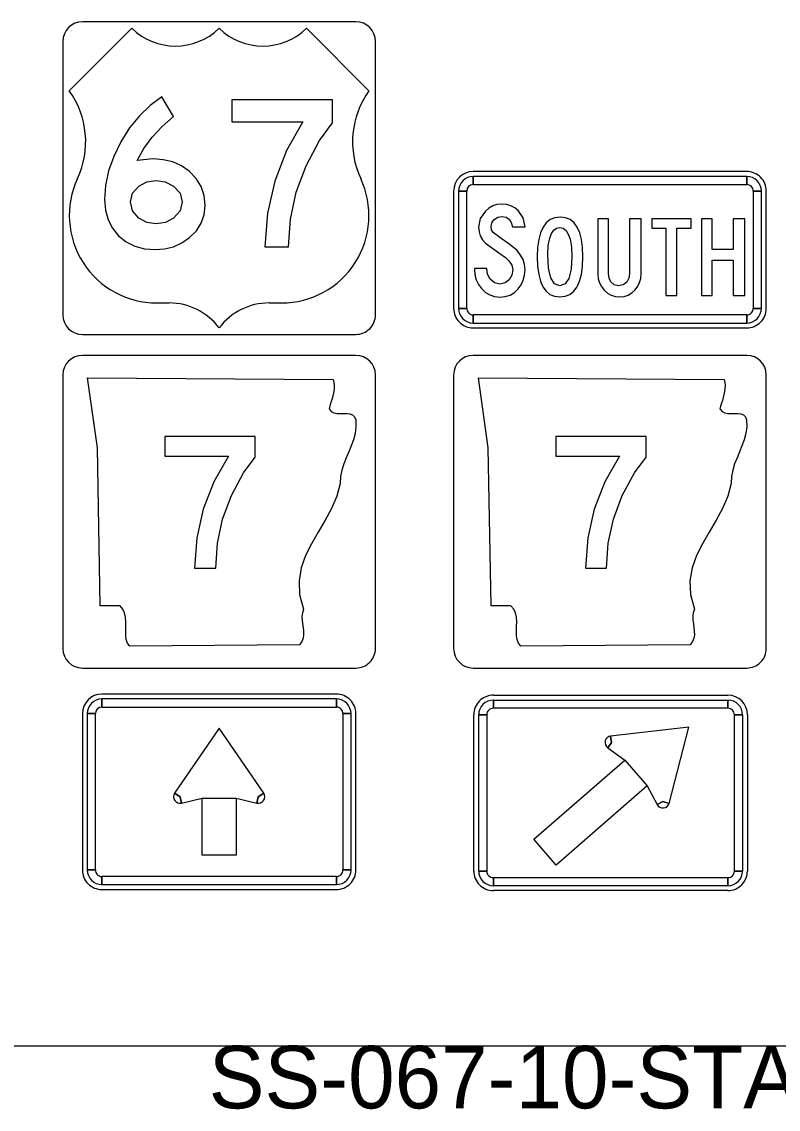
# Model space of a CAD drawing. Extents: x 1001568 to 1002149, y 1840825 to 1841423.
# Drawn here: x 1001897.59 to 1001902.43, y 1841195.06 to 1841202.02 of the extents above; entities that cross this region are included whole.
import ezdxf

# ---------------------------------------------------------------- set-up
doc = ezdxf.new("R2010")
doc.units = 0
for name, color, linetype in [('40', 7, 'Continuous'), ('R_No Plot', 7, 'Continuous'), ('SIGNS', 7, 'Continuous')]:
    doc.layers.add(name, color=color, linetype=linetype)

msp = doc.modelspace()

# ---------------------------------------------------------------- linework, layer by layer
at = {"layer": 'R_No Plot'}
msp.add_line((1001886.4111, 1841195.4691), (1001982.1327, 1841195.4691), dxfattribs=at)
at = {"layer": 'SIGNS'}
for p, q in [((1001899.7246, 1841202.0197), (1001897.9746, 1841202.0197)), ((1001898.2906, 1841201.9781), (1001897.8913, 1841201.5788)), ((1001899.8079, 1841201.5788), (1001899.4086, 1841201.9781)), ((1001897.8496, 1841201.8947), (1001897.8496, 1841200.1447)), ((1001899.8496, 1841200.1447), (1001899.8496, 1841201.8947)), ((1001902.2246, 1841201.0614), (1001900.4746, 1841201.0614)), ((1001900.4746, 1841200.9781), (1001900.4746, 1841201.0302)), ((1001902.2246, 1841201.0302), (1001902.2246, 1841200.9781)), ((1001900.3496, 1841200.9364), (1001900.3496, 1841200.1864)), ((1001900.3808, 1841200.9364), (1001900.4329, 1841200.9364)), ((1001902.2663, 1841200.9364), (1001902.3183, 1841200.9364)), ((1001902.3496, 1841200.1864), (1001902.3496, 1841200.9364)), ((1001898.4503, 1841200.2211), (1001898.5301, 1841200.2211)), ((1001899.169, 1841200.2211), (1001899.2489, 1841200.2211)), ((1001897.8496, 1841200.1447), (1001897.8496, 1841200.1447)), ((1001900.4329, 1841200.1864), (1001900.3808, 1841200.1864)), ((1001900.4746, 1841200.0927), (1001900.4746, 1841200.1447)), ((1001902.2246, 1841200.1447), (1001902.2246, 1841200.0927)), ((1001902.3183, 1841200.1864), (1001902.2663, 1841200.1864)), ((1001897.9746, 1841200.0197), (1001899.7246, 1841200.0197)), ((1001900.4746, 1841200.0614), (1001902.2246, 1841200.0614)), ((1001899.7246, 1841199.8858), (1001897.9746, 1841199.8858)), ((1001902.2246, 1841199.8858), (1001900.4746, 1841199.8858)), ((1001897.8496, 1841199.7608), (1001897.8496, 1841198.0108)), ((1001899.8496, 1841198.0108), (1001899.8496, 1841199.7608)), ((1001900.3496, 1841199.7608), (1001900.3496, 1841198.0108)), ((1001902.3496, 1841198.0108), (1001902.3496, 1841199.7608)), ((1001897.8496, 1841198.0108), (1001897.8496, 1841198.0108)), ((1001900.3496, 1841198.0108), (1001900.3496, 1841198.0108)), ((1001897.9746, 1841197.8858), (1001899.7246, 1841197.8858)), ((1001900.4746, 1841197.8858), (1001902.2246, 1841197.8858)), ((1001899.5996, 1841197.7191), (1001898.0996, 1841197.7191)), ((1001900.6035, 1841197.712), (1001902.1035, 1841197.712)), ((1001898.0996, 1841197.6358), (1001898.0996, 1841197.6879)), ((1001899.5996, 1841197.6879), (1001899.5996, 1841197.6358)), ((1001900.6035, 1841197.6808), (1001900.6035, 1841197.6287)), ((1001902.1035, 1841197.6287), (1001902.1035, 1841197.6808)), ((1001897.9746, 1841197.5941), (1001897.9746, 1841196.5941)), ((1001898.0058, 1841197.5941), (1001898.0579, 1841197.5941)), ((1001899.6413, 1841197.5941), (1001899.6933, 1841197.5941)), ((1001899.7246, 1841196.5941), (1001899.7246, 1841197.5941)), ((1001900.4785, 1841196.587), (1001900.4785, 1841197.587)), ((1001900.5618, 1841197.587), (1001900.5098, 1841197.587)), ((1001902.1973, 1841197.587), (1001902.1452, 1841197.587)), ((1001902.2285, 1841197.587), (1001902.2285, 1841196.587)), ((1001901.3599, 1841197.4094), (1001901.3536, 1841197.4506)), ((1001901.3354, 1841197.3757), (1001901.3599, 1841197.4094)), ((1001898.5996, 1841197.0629), (1001898.5644, 1841197.0851)), ((1001899.1348, 1841197.0851), (1001899.0996, 1841197.0629)), ((1001898.6089, 1841197.0223), (1001898.5996, 1841197.0629)), ((1001899.0996, 1841197.0629), (1001899.0902, 1841197.0223)), ((1001901.688, 1841197.0321), (1001901.6512, 1841197.0125)), ((1001901.7279, 1841197.0201), (1001901.688, 1841197.0321)), ((1001898.0579, 1841196.5941), (1001898.0058, 1841196.5941)), ((1001899.6933, 1841196.5941), (1001899.6413, 1841196.5941)), ((1001898.0996, 1841196.5004), (1001898.0996, 1841196.5524)), ((1001899.5996, 1841196.5524), (1001899.5996, 1841196.5004)), ((1001900.5098, 1841196.587), (1001900.5618, 1841196.587)), ((1001900.6035, 1841196.5454), (1001900.6035, 1841196.4933)), ((1001902.1035, 1841196.4933), (1001902.1035, 1841196.5454)), ((1001902.1452, 1841196.587), (1001902.1973, 1841196.587)), ((1001898.0996, 1841196.4691), (1001899.5996, 1841196.4691)), ((1001902.1035, 1841196.462), (1001900.6035, 1841196.462))]:
    msp.add_line(p, q, dxfattribs=at)
for points in [[(1001897.9746, 1841202.0197), (1001897.9746, 1841202.0197)], [(1001899.7246, 1841202.0197), (1001899.7246, 1841202.0197)], [(1001897.8496, 1841201.8947), (1001897.8496, 1841201.8947)], [(1001898.5582, 1841201.4144), (1001898.4824, 1841201.5388), (1001898.4075, 1841201.4835), (1001898.3393, 1841201.4175), (1001898.2771, 1841201.3401), (1001898.2215, 1841201.252), (1001898.1752, 1841201.1584), (1001898.1427, 1841201.0654), (1001898.1228, 1841200.9732), (1001898.1165, 1841200.882), (1001898.1218, 1841200.8142), (1001898.1389, 1841200.7532), (1001898.1671, 1841200.6988), (1001898.2068, 1841200.651), (1001898.2552, 1841200.6119), (1001898.3102, 1841200.5842), (1001898.3715, 1841200.5676), (1001898.4395, 1841200.5621), (1001898.5003, 1841200.5667), (1001898.5576, 1841200.581), (1001898.6102, 1841200.605), (1001898.6595, 1841200.6389), (1001898.7038, 1841200.6824), (1001898.7355, 1841200.7313), (1001898.7545, 1841200.7855), (1001898.7608, 1841200.8451), (1001898.7543, 1841200.9088), (1001898.7352, 1841200.9665), (1001898.703, 1841201.0181), (1001898.6583, 1841201.0636), (1001898.6079, 1841201.0979), (1001898.5529, 1841201.1227), (1001898.4924, 1841201.1373), (1001898.4272, 1841201.1425), (1001898.3257, 1841201.1322), (1001898.3681, 1841201.2094), (1001898.4211, 1841201.2825), (1001898.4844, 1841201.3505), (1001898.5582, 1841201.4144)], [(1001898.2822, 1841200.867), (1001898.2956, 1841200.9231), (1001898.3358, 1841200.9689), (1001898.388, 1841200.9954), (1001898.4467, 1841201.0043), (1001898.5054, 1841200.9954), (1001898.5584, 1841200.9689), (1001898.5998, 1841200.9234), (1001898.614, 1841200.867), (1001898.5998, 1841200.8093), (1001898.5584, 1841200.7633), (1001898.506, 1841200.7366), (1001898.4467, 1841200.7279), (1001898.3874, 1841200.7366), (1001898.3358, 1841200.7633), (1001898.2956, 1841200.8093), (1001898.2822, 1841200.867)], [(1001901.1765, 1841200.5156), (1001901.1741, 1841200.575), (1001901.1673, 1841200.6267), (1001901.1561, 1841200.6703), (1001901.1403, 1841200.7061), (1001901.1197, 1841200.7338), (1001901.0949, 1841200.7538), (1001901.0655, 1841200.7656), (1001901.0317, 1841200.7697), (1001900.9971, 1841200.7656), (1001900.9672, 1841200.7538), (1001900.9419, 1841200.7338), (1001900.9214, 1841200.7061), (1001900.9053, 1841200.6703), (1001900.8939, 1841200.6267), (1001900.8869, 1841200.575), (1001900.8848, 1841200.5156), (1001900.8868, 1841200.4555), (1001900.8936, 1841200.4037), (1001900.9048, 1841200.3597), (1001900.9206, 1841200.3239), (1001900.9408, 1841200.2959), (1001900.9656, 1841200.276), (1001900.9949, 1841200.2641), (1001901.0287, 1841200.2602), (1001901.0632, 1841200.2641), (1001901.0932, 1841200.276), (1001901.1186, 1841200.2959), (1001901.1395, 1841200.3239), (1001901.1556, 1841200.3597), (1001901.1672, 1841200.4037), (1001901.1741, 1841200.4555), (1001901.1765, 1841200.5156)], [(1001901.1059, 1841200.5179), (1001901.1011, 1841200.4362), (1001901.0867, 1841200.378), (1001901.0627, 1841200.343), (1001901.0294, 1841200.3314), (1001900.9955, 1841200.3438), (1001900.9712, 1841200.3811), (1001900.9568, 1841200.4431), (1001900.952, 1841200.5302), (1001900.9551, 1841200.5881), (1001900.9643, 1841200.6361), (1001900.9755, 1841200.6656), (1001900.99, 1841200.6869), (1001901.0079, 1841200.6995), (1001901.0294, 1841200.7039), (1001901.0505, 1841200.6992), (1001901.0683, 1841200.6853), (1001901.0829, 1841200.662), (1001901.0942, 1841200.6297), (1001901.1029, 1841200.5788), (1001901.1059, 1841200.5179)], [(1001897.9746, 1841200.0197), (1001897.9746, 1841200.0197)], [(1001899.7246, 1841200.0197), (1001899.7246, 1841200.0197)], [(1001897.9746, 1841199.8858), (1001897.9746, 1841199.8858)], [(1001899.7246, 1841199.8858), (1001899.7246, 1841199.8858)], [(1001900.4746, 1841199.8858), (1001900.4746, 1841199.8858)], [(1001902.2246, 1841199.8858), (1001902.2246, 1841199.8858)], [(1001897.8496, 1841199.7608), (1001897.8496, 1841199.7608)], [(1001900.3496, 1841199.7608), (1001900.3496, 1841199.7608)], [(1001897.9746, 1841197.8858), (1001897.9746, 1841197.8858)], [(1001899.7246, 1841197.8858), (1001899.7246, 1841197.8858)], [(1001900.4746, 1841197.8858), (1001900.4746, 1841197.8858)], [(1001902.2246, 1841197.8858), (1001902.2246, 1841197.8858)]]:
    msp.add_lwpolyline(points, dxfattribs=at)
for points in [[(1001899.1423, 1841200.5805), (1001899.2942, 1841200.5805), (1001899.3062, 1841200.7573), (1001899.3433, 1841200.93), (1001899.4053, 1841201.0976), (1001899.492, 1841201.2609), (1001899.5754, 1841201.373), (1001899.5754, 1841201.5204), (1001898.931, 1841201.5204), (1001898.931, 1841201.3795), (1001899.3851, 1841201.3795), (1001899.2802, 1841201.1953), (1001899.2051, 1841201.0008), (1001899.159, 1841200.7959)], [(1001902.2246, 1841201.0302), (1001900.4746, 1841201.0302), (1001900.4746, 1841200.9781), (1001902.2246, 1841200.9781), (1001902.2246, 1841201.0302), (1001902.2246, 1841201.0302)], [(1001900.3808, 1841200.9364), (1001900.3808, 1841200.1864), (1001900.4329, 1841200.1864), (1001900.4329, 1841200.9364), (1001900.3808, 1841200.9364), (1001900.3808, 1841200.9364)], [(1001902.3183, 1841200.1864), (1001902.3183, 1841200.9364), (1001902.2663, 1841200.9364), (1001902.2663, 1841200.1864), (1001902.3183, 1841200.1864), (1001902.3183, 1841200.1864)], [(1001900.4833, 1841200.4416), (1001900.4833, 1841200.4364), (1001900.4857, 1841200.4015), (1001900.4939, 1841200.3693), (1001900.508, 1841200.3397), (1001900.5275, 1841200.3127), (1001900.5523, 1841200.2888), (1001900.5803, 1841200.272), (1001900.6111, 1841200.2619), (1001900.6453, 1841200.2586), (1001900.6794, 1841200.2617), (1001900.7104, 1841200.2717), (1001900.7379, 1841200.288), (1001900.7625, 1841200.311), (1001900.7815, 1841200.3375), (1001900.7952, 1841200.3668), (1001900.8035, 1841200.3986), (1001900.8063, 1841200.4332), (1001900.8029, 1841200.4663), (1001900.7933, 1841200.4979), (1001900.7772, 1841200.5277), (1001900.7549, 1841200.5559), (1001900.7118, 1841200.5931), (1001900.6453, 1841200.6387), (1001900.6014, 1841200.6716), (1001900.5919, 1841200.6883), (1001900.5887, 1841200.7074), (1001900.5938, 1841200.7329), (1001900.6092, 1841200.7545), (1001900.6315, 1841200.769), (1001900.658, 1841200.774), (1001900.6863, 1841200.7693), (1001900.7071, 1841200.7556), (1001900.7182, 1841200.7361), (1001900.7267, 1841200.7075), (1001900.8063, 1841200.7075), (1001900.7933, 1841200.7659), (1001900.763, 1841200.8118), (1001900.7407, 1841200.8297), (1001900.7157, 1841200.8427), (1001900.687, 1841200.8504), (1001900.6557, 1841200.8531), (1001900.6266, 1841200.8502), (1001900.5997, 1841200.842), (1001900.5749, 1841200.8281), (1001900.5525, 1841200.8089), (1001900.5199, 1841200.7609), (1001900.5092, 1841200.7051), (1001900.5118, 1841200.6763), (1001900.52, 1841200.6501), (1001900.5337, 1841200.6257), (1001900.553, 1841200.6036), (1001900.6459, 1841200.5372), (1001900.6804, 1841200.5109), (1001900.7018, 1841200.4914), (1001900.7207, 1841200.4629), (1001900.7272, 1841200.4324), (1001900.7216, 1841200.3986), (1001900.7053, 1841200.3698), (1001900.6783, 1841200.3488), (1001900.6453, 1841200.3417), (1001900.6101, 1841200.3495), (1001900.5829, 1841200.3729), (1001900.567, 1841200.4042), (1001900.5623, 1841200.4416)], [(1001901.2719, 1841200.7601), (1001901.2719, 1841200.4051), (1001901.2747, 1841200.3762), (1001901.2825, 1841200.3496), (1001901.2952, 1841200.3252), (1001901.3129, 1841200.3028), (1001901.3339, 1841200.284), (1001901.3577, 1841200.2708), (1001901.3838, 1841200.2627), (1001901.4124, 1841200.2602), (1001901.44, 1841200.2628), (1001901.4657, 1841200.2712), (1001901.489, 1841200.2852), (1001901.5102, 1841200.3049), (1001901.527, 1841200.3274), (1001901.539, 1841200.3519), (1001901.5462, 1841200.3782), (1001901.5488, 1841200.4066), (1001901.5488, 1841200.7601), (1001901.4738, 1841200.7601), (1001901.4738, 1841200.4094), (1001901.4694, 1841200.3786), (1001901.4567, 1841200.3545), (1001901.4343, 1841200.3369), (1001901.405, 1841200.331), (1001901.3772, 1841200.337), (1001901.3559, 1841200.3555), (1001901.3433, 1841200.38), (1001901.3392, 1841200.4094), (1001901.3392, 1841200.7601)], [(1001901.706, 1841200.2697), (1001901.7771, 1841200.2697), (1001901.7771, 1841200.6985), (1001901.8686, 1841200.6985), (1001901.8686, 1841200.7601), (1001901.6164, 1841200.7601), (1001901.6164, 1841200.6985), (1001901.706, 1841200.6985)], [(1001901.9359, 1841200.2697), (1001902.0032, 1841200.2697), (1001902.0032, 1841200.4948), (1001902.1378, 1841200.4948), (1001902.1378, 1841200.2697), (1001902.2128, 1841200.2697), (1001902.2128, 1841200.7601), (1001902.1378, 1841200.7601), (1001902.1378, 1841200.5634), (1001902.0032, 1841200.5634), (1001902.0032, 1841200.7601), (1001901.9359, 1841200.7601)], [(1001900.4746, 1841200.0927), (1001902.2246, 1841200.0927), (1001902.2246, 1841200.1447), (1001900.4746, 1841200.1447), (1001900.4746, 1841200.0927), (1001900.4746, 1841200.0927)], [(1001899.5795, 1841199.7314), (1001899.5842, 1841199.7123), (1001899.5858, 1841199.6928), (1001899.5852, 1841199.6737), (1001899.5828, 1841199.6546), (1001899.5788, 1841199.6356), (1001899.5741, 1841199.6168), (1001899.5684, 1841199.5978), (1001899.5628, 1841199.5794), (1001899.5574, 1841199.561), (1001899.5524, 1841199.5427), (1001899.5664, 1841199.5265), (1001899.5838, 1841199.5174), (1001899.6035, 1841199.5133), (1001899.625, 1841199.5129), (1001899.6463, 1841199.5137), (1001899.6671, 1841199.514), (1001899.6861, 1841199.5118), (1001899.7028, 1841199.5056), (1001899.7158, 1841199.4935), (1001899.7238, 1841199.4733), (1001899.7245, 1841199.4278), (1001899.7188, 1841199.3852), (1001899.7082, 1841199.3448), (1001899.6938, 1841199.3063), (1001899.6781, 1841199.2681), (1001899.662, 1841199.2303), (1001899.647, 1841199.1917), (1001899.635, 1841199.1521), (1001899.6266, 1841199.1106), (1001899.6246, 1841199.0665), (1001899.6025, 1841198.9843), (1001899.5688, 1841198.9061), (1001899.528, 1841198.8305), (1001899.4839, 1841198.7556), (1001899.4408, 1841198.6811), (1001899.403, 1841198.6051), (1001899.375, 1841198.5265), (1001899.3606, 1841198.4439), (1001899.3639, 1841198.3565), (1001899.3897, 1841198.2629), (1001899.382, 1841198.2398), (1001899.3793, 1841198.2159), (1001899.38, 1841198.1921), (1001899.383, 1841198.1678), (1001899.3863, 1841198.144), (1001899.389, 1841198.1205), (1001899.3897, 1841198.0974), (1001899.3863, 1841198.0757), (1001899.378, 1841198.0544), (1001899.3626, 1841198.0346), (1001898.2789, 1841198.0247), (1001898.2642, 1841198.0445), (1001898.2558, 1841198.0683), (1001898.2522, 1841198.0948), (1001898.2518, 1841198.123), (1001898.2525, 1841198.1528), (1001898.2528, 1841198.1822), (1001898.2508, 1841198.2112), (1001898.2451, 1841198.2379), (1001898.2341, 1841198.2622), (1001898.2157, 1841198.2827), (1001898.0894, 1841198.2827), (1001898.0714, 1841199.2945), (1001898.0079, 1841199.7413), (1001899.5795, 1841199.7314), (1001899.5795, 1841199.7314)], [(1001902.0795, 1841199.7314), (1001902.0842, 1841199.7123), (1001902.0859, 1841199.6928), (1001902.0852, 1841199.6737), (1001902.0828, 1841199.6546), (1001902.0788, 1841199.6356), (1001902.0741, 1841199.6168), (1001902.0684, 1841199.5978), (1001902.0628, 1841199.5794), (1001902.0574, 1841199.561), (1001902.0524, 1841199.5427), (1001902.0664, 1841199.5265), (1001902.0838, 1841199.5174), (1001902.1035, 1841199.5133), (1001902.125, 1841199.5129), (1001902.1463, 1841199.5137), (1001902.1671, 1841199.514), (1001902.1861, 1841199.5118), (1001902.2028, 1841199.5056), (1001902.2158, 1841199.4935), (1001902.2238, 1841199.4733), (1001902.2245, 1841199.4278), (1001902.2188, 1841199.3852), (1001902.2082, 1841199.3448), (1001902.1938, 1841199.3063), (1001902.1781, 1841199.2681), (1001902.162, 1841199.2303), (1001902.147, 1841199.1917), (1001902.135, 1841199.1521), (1001902.1266, 1841199.1106), (1001902.1246, 1841199.0665), (1001902.1025, 1841198.9843), (1001902.0688, 1841198.9061), (1001902.028, 1841198.8305), (1001901.9839, 1841198.7556), (1001901.9408, 1841198.6811), (1001901.903, 1841198.6051), (1001901.875, 1841198.5265), (1001901.8606, 1841198.4439), (1001901.8639, 1841198.3565), (1001901.8897, 1841198.2629), (1001901.882, 1841198.2398), (1001901.8793, 1841198.2159), (1001901.88, 1841198.1921), (1001901.883, 1841198.1678), (1001901.8863, 1841198.144), (1001901.889, 1841198.1205), (1001901.8897, 1841198.0974), (1001901.8863, 1841198.0757), (1001901.878, 1841198.0544), (1001901.8626, 1841198.0346), (1001900.7789, 1841198.0247), (1001900.7642, 1841198.0445), (1001900.7558, 1841198.0683), (1001900.7522, 1841198.0948), (1001900.7518, 1841198.123), (1001900.7525, 1841198.1528), (1001900.7528, 1841198.1822), (1001900.7508, 1841198.2112), (1001900.7451, 1841198.2379), (1001900.7341, 1841198.2622), (1001900.7157, 1841198.2827), (1001900.5894, 1841198.2827), (1001900.5714, 1841199.2945), (1001900.5079, 1841199.7413), (1001902.0795, 1841199.7314), (1001902.0795, 1841199.7314)], [(1001898.6921, 1841198.5253), (1001898.8281, 1841198.5253), (1001898.8389, 1841198.6836), (1001898.8721, 1841198.8384), (1001898.9276, 1841198.9884), (1001899.0053, 1841199.1347), (1001899.08, 1841199.2351), (1001899.08, 1841199.3671), (1001898.5029, 1841199.3671), (1001898.5029, 1841199.2409), (1001898.9095, 1841199.2409), (1001898.8156, 1841199.0759), (1001898.7484, 1841198.9018), (1001898.7071, 1841198.7182)], [(1001901.1921, 1841198.5253), (1001901.3281, 1841198.5253), (1001901.3389, 1841198.6836), (1001901.3721, 1841198.8384), (1001901.4276, 1841198.9884), (1001901.5053, 1841199.1347), (1001901.58, 1841199.2351), (1001901.58, 1841199.3671), (1001901.0029, 1841199.3671), (1001901.0029, 1841199.2409), (1001901.4095, 1841199.2409), (1001901.3156, 1841199.0759), (1001901.2484, 1841198.9018), (1001901.2071, 1841198.7182)], [(1001899.5996, 1841197.6879), (1001898.0996, 1841197.6879), (1001898.0996, 1841197.6358), (1001899.5996, 1841197.6358), (1001899.5996, 1841197.6879), (1001899.5996, 1841197.6879)], [(1001900.6035, 1841197.6808), (1001902.1035, 1841197.6808), (1001902.1035, 1841197.6287), (1001900.6035, 1841197.6287), (1001900.6035, 1841197.6808), (1001900.6035, 1841197.6808)], [(1001898.0058, 1841197.5941), (1001898.0058, 1841196.5941), (1001898.0579, 1841196.5941), (1001898.0579, 1841197.5941), (1001898.0058, 1841197.5941), (1001898.0058, 1841197.5941)], [(1001899.6933, 1841196.5941), (1001899.6933, 1841197.5941), (1001899.6413, 1841197.5941), (1001899.6413, 1841196.5941), (1001899.6933, 1841196.5941), (1001899.6933, 1841196.5941)], [(1001900.5098, 1841196.587), (1001900.5098, 1841197.587), (1001900.5618, 1841197.587), (1001900.5618, 1841196.587), (1001900.5098, 1841196.587), (1001900.5098, 1841196.587)], [(1001902.1973, 1841197.587), (1001902.1973, 1841196.587), (1001902.1452, 1841196.587), (1001902.1452, 1841197.587), (1001902.1973, 1841197.587), (1001902.1973, 1841197.587)], [(1001898.8496, 1841197.5004), (1001898.5644, 1841197.0851), (1001898.5996, 1841197.0629), (1001898.6089, 1841197.0223), (1001898.7402, 1841197.0524), (1001898.959, 1841197.0524), (1001899.0902, 1841197.0223), (1001899.0996, 1841197.0629), (1001899.1348, 1841197.0851), (1001898.8496, 1841197.5004), (1001898.8496, 1841197.5004)], [(1001901.8541, 1841197.5078), (1001901.3536, 1841197.4506), (1001901.3599, 1841197.4094), (1001901.3354, 1841197.3757), (1001901.4443, 1841197.2965), (1001901.5878, 1841197.1314), (1001901.6512, 1841197.0125), (1001901.688, 1841197.0321), (1001901.7279, 1841197.0201), (1001901.8541, 1841197.5078)], [(1001901.0061, 1841196.6257), (1001900.8626, 1841196.7908), (1001901.4443, 1841197.2965), (1001901.5878, 1841197.1314), (1001901.0061, 1841196.6257)], [(1001898.959, 1841196.6879), (1001898.7402, 1841196.6879), (1001898.7402, 1841197.0524), (1001898.959, 1841197.0524), (1001898.959, 1841196.6879), (1001898.959, 1841196.6879)], [(1001898.0996, 1841196.5004), (1001899.5996, 1841196.5004), (1001899.5996, 1841196.5524), (1001898.0996, 1841196.5524), (1001898.0996, 1841196.5004), (1001898.0996, 1841196.5004)], [(1001902.1035, 1841196.4933), (1001900.6035, 1841196.4933), (1001900.6035, 1841196.5454), (1001902.1035, 1841196.5454), (1001902.1035, 1841196.4933), (1001902.1035, 1841196.4933)]]:
    msp.add_lwpolyline(points, close=True, dxfattribs=at)
for centre, radius, start, end in [((1001897.9746, 1841201.8947), 0.125, 90.00021, 179.99985), ((1001899.7246, 1841201.8947), 0.125, 0, 90), ((1001898.5701, 1841202.2633), 0.3993, 225.57291, 314.42721), ((1001899.1291, 1841202.2633), 0.3993, 225.57291, 314.42721), ((1001897.4371, 1841201.2528), 0.559, 334.98952, 35.66288), ((1001900.2621, 1841201.2528), 0.559, 144.33724, 205.01003), ((1001900.4746, 1841200.9364), 0.125, 90.00021, 179.99985), ((1001902.2246, 1841200.9364), 0.125, 360, 90.00021), ((1001898.4503, 1841200.7802), 0.559, 154.98967, 270.00006), ((1001899.2489, 1841200.7802), 0.559, 270.00006, 25.01045), ((1001900.4746, 1841200.9364), 0.0937, 90.00021, 179.99985), ((1001900.4746, 1841200.9364), 0.0417, 90.00021, 179.99985), ((1001902.2246, 1841200.9364), 0.0937, 360, 90.00021), ((1001902.2246, 1841200.9364), 0.0417, 360, 90.00021), ((1001898.5301, 1841199.8218), 0.3993, 36.86989, 90.00021), ((1001899.169, 1841199.8218), 0.3993, 90.00021, 143.13001), ((1001897.9746, 1841200.1447), 0.125, 180, 270), ((1001899.7246, 1841200.1447), 0.125, 270.00006, 0.00027), ((1001900.4746, 1841200.1864), 0.125, 179.99985, 270.00006), ((1001900.4746, 1841200.1864), 0.0937, 179.99985, 270.00006), ((1001900.4746, 1841200.1864), 0.0417, 179.99985, 270.00006), ((1001902.2246, 1841200.1864), 0.125, 270.00006, 0.00027), ((1001902.2246, 1841200.1864), 0.0937, 270.00006, 0.00027), ((1001902.2246, 1841200.1864), 0.0417, 270.00006, 0.00027), ((1001897.9746, 1841199.7608), 0.125, 90.00021, 179.99985), ((1001899.7246, 1841199.7608), 0.125, 0, 90), ((1001900.4746, 1841199.7608), 0.125, 90.00021, 179.99985), ((1001902.2246, 1841199.7608), 0.125, 0, 90), ((1001897.9746, 1841198.0108), 0.125, 180, 270), ((1001899.7246, 1841198.0108), 0.125, 270.00006, 0.00027), ((1001900.4746, 1841198.0108), 0.125, 180, 270), ((1001902.2246, 1841198.0108), 0.125, 270.00006, 0.00027), ((1001898.0996, 1841197.5941), 0.125, 90.00021, 179.99985), ((1001899.5996, 1841197.5941), 0.125, 0, 90.00021), ((1001900.6035, 1841197.587), 0.125, 89.99979, 180), ((1001902.1035, 1841197.587), 0.125, 0.00015, 89.99979), ((1001898.0996, 1841197.5941), 0.0937, 90.00021, 179.99985), ((1001898.0996, 1841197.5941), 0.0417, 90.00021, 179.99985), ((1001899.5996, 1841197.5941), 0.0937, 0, 90.00021), ((1001899.5996, 1841197.5941), 0.0417, 0, 90.00021), ((1001900.6035, 1841197.587), 0.0937, 89.99979, 180), ((1001902.1035, 1841197.587), 0.0937, 0.00015, 89.99979), ((1001900.6035, 1841197.587), 0.0417, 89.99979, 180), ((1001902.1035, 1841197.587), 0.0417, 0.00015, 89.99979), ((1001901.3599, 1841197.4094), 0.0417, 98.72435, 233.95041), ((1001898.5996, 1841197.0629), 0.0417, 147.72456, 282.95062), ((1001899.0996, 1841197.0629), 0.0417, 257.04949, 32.27555), ((1001901.688, 1841197.0321), 0.0417, 208.04986, 343.27592), ((1001898.0996, 1841196.5941), 0.125, 179.99985, 270.00006), ((1001898.0996, 1841196.5941), 0.0937, 179.99985, 270.00006), ((1001898.0996, 1841196.5941), 0.0417, 179.99985, 270.00006), ((1001899.5996, 1841196.5941), 0.0937, 270.00006, 0.00027), ((1001899.5996, 1841196.5941), 0.0417, 270.00006, 0.00027), ((1001899.5996, 1841196.5941), 0.125, 270.00006, 0.00027), ((1001900.6035, 1841196.587), 0.125, 179.99973, 269.99994), ((1001900.6035, 1841196.587), 0.0937, 179.99973, 269.99994), ((1001900.6035, 1841196.587), 0.0417, 179.99973, 269.99994), ((1001902.1035, 1841196.587), 0.0937, 269.99994, 0.00015), ((1001902.1035, 1841196.587), 0.0417, 269.99994, 0.00015), ((1001902.1035, 1841196.587), 0.125, 269.99994, 0.00015)]:
    msp.add_arc(centre, radius, start, end, dxfattribs=at)

# ---------------------------------------------------------------- texts
at = {"layer": '40'}
msp.add_text('SS-067-10-STA144+50NB', height=0.4, rotation=0, dxfattribs=at).set_placement((1001898.7829, 1841195.0691))

doc.saveas('drawing.dxf')
